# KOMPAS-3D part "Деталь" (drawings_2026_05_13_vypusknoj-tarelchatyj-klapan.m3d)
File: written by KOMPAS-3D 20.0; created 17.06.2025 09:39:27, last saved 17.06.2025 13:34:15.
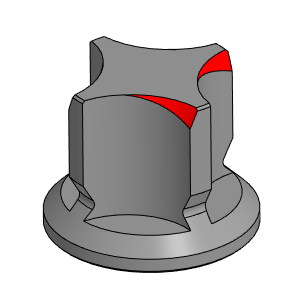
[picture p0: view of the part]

Document properties: Автор: VLAD; Полное имя файла: C:\Users\VLAD\Desktop\Выпускной тарельчатый клапан.m3d

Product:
- Part/product: Деталь
    Масса: 0.162772

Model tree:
1. Эскиз:1
2. Элемент вращения:1
     Угол 1 = 360
3. Эскиз:4  (with: Элемент вращения:1)
4. Элемент выдавливания:2
     Расстояние 2 = 26
5. Массив по концентрической сетке:3  (with: Элемент выдавливания:2, Элемент вращения:1)  (4 pattern instances)
     Шаг 2 = 360
6. Касательная плоскость:2  (with: Элемент вращения:1)
7. Эскиз:12
8. Эскиз:13  (with: Элемент вращения:1)
9. Элемент по траектории:6
10. Массив по концентрической сетке:6  (with: Элемент по траектории:6, Касательная плоскость:2, Элемент вращения:1)  (4 pattern instances)
     Шаг 2 = 360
